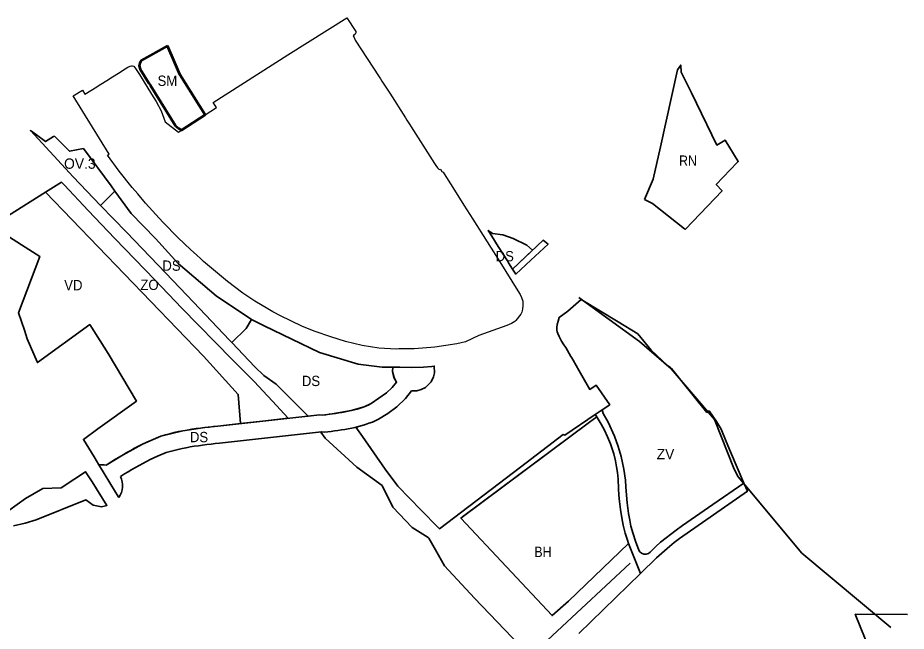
# Model space of a CAD drawing. Extents: x -650276 to -642489, y -1074311 to -1066658.
# Drawn here: x -647227 to -646196, y -1072424 to -1071711 of the extents above; entities that cross this region are included whole.
import ezdxf

# ---------------------------------------------------------------- set-up
doc = ezdxf.new("R2010")
doc.units = 0
doc.header["$LTSCALE"] = 4.8
for name, color, linetype, lineweight in [('1', 7, 'Continuous', 35), ('11', 7, 'Continuous', 35), ('15', 7, 'Continuous', 35), ('18', 7, 'Continuous', 35), ('24', 7, 'Continuous', 35), ('35', 7, 'Continuous', 35), ('40', 7, 'Continuous', 35), ('42', 7, 'Continuous', 35), ('48', 7, 'Continuous', 35), ('54', 7, 'Continuous', 35), ('60', 7, 'Continuous', 53), ('61', 7, 'Continuous', 25), ('7', 7, 'Continuous', 35)]:
    doc.layers.add(name, color=color, linetype=linetype, lineweight=lineweight)
doc.layers.add('62', color=7, linetype='Continuous')

msp = doc.modelspace()

# ---------------------------------------------------------------- linework, layer by layer
at = {"layer": '1'}
msp.add_lwpolyline([(-646606.848, -1072405.785), (-646587.666, -1072389.082), (-646518.208, -1072321.92), (-646519.417, -1072318.408), (-646522.007, -1072309.932), (-646524.282, -1072300.849), (-646526, -1072292.201), (-646527.5, -1072282.657), (-646528.566, -1072273.308), (-646529.182, -1072265.941), (-646529.607, -1072258.124), (-646530.188, -1072247.442), (-646530.892, -1072239.747), (-646531.93, -1072232.861), (-646533.286, -1072226.031), (-646535.344, -1072217.844), (-646536.772, -1072213.218), (-646539.168, -1072206.122), (-646539.168, -1072206.122), (-646542.484, -1072197.985), (-646546.09, -1072190.428), (-646549.793, -1072183.38), (-646554.56, -1072175.629), (-646555.051, -1072174.933), (-646563.299, -1072181.091), (-646710.684, -1072291.133), (-646712.634, -1072292.59)], close=True, dxfattribs=at)
at = {"layer": '11'}
for points in [[(-647184.81, -1071848.61), (-647185.62, -1071849.12), (-647194.96, -1071854.93), (-647205.62, -1071847.24), (-647212.66, -1071842.15), (-647163.08, -1071896.13), (-647131.146, -1071929.146)], [(-647131.146, -1071929.146), (-647114.479, -1071912.479), (-647118.79, -1071906.59), (-647151.07, -1071863.08), (-647167.15, -1071866.22), (-647184.81, -1071848.61)]]:
    msp.add_lwpolyline(points, dxfattribs=at)
at = {"layer": '15'}
for points in [[(-646652.864, -1072003.075), (-646617.21, -1071969.689), (-646611.438, -1071974.36), (-646631.409, -1071992.798), (-646649.112, -1072009.049)], [(-646529.182, -1072265.941), (-646528.566, -1072273.308), (-646527.5, -1072282.657), (-646526, -1072292.201), (-646524.282, -1072300.849), (-646522.007, -1072309.932), (-646519.417, -1072318.408), (-646518.208, -1072321.92), (-646504.244, -1072357.026), (-646485.656, -1072338.908), (-646473.069, -1072327.765), (-646465.227, -1072321.127), (-646459.03, -1072316.137), (-646380.12, -1072261.44), (-646384.056, -1072252.138), (-646420.085, -1072276.737), (-646455.557, -1072301.131), (-646462.79, -1072306.784), (-646480.923, -1072320.667), (-646486.273, -1072325.526), (-646492.813, -1072332.07), (-646494.794, -1072333.558), (-646497.569, -1072334.55), (-646500.244, -1072334.45), (-646503.018, -1072333.459), (-646504.802, -1072331.971), (-646506.189, -1072329.889), (-646509.954, -1072319.377), (-646512.729, -1072311.048), (-646515.305, -1072301.925), (-646516.692, -1072294.983), (-646518.079, -1072287.051), (-646519.756, -1072274.861), (-646521.051, -1072256.707), (-646521.646, -1072248.378), (-646523.628, -1072235.883), (-646526.798, -1072221.011), (-646530.167, -1072209.31), (-646534.527, -1072197.411), (-646541.822, -1072181.102), (-646547.606, -1072170.835), (-646548.676, -1072166.737), (-646556.693, -1072172.16), (-646555.051, -1072174.933), (-646554.56, -1072175.629), (-646549.793, -1072183.38), (-646546.09, -1072190.428), (-646542.484, -1072197.985), (-646539.168, -1072206.122), (-646536.772, -1072213.218), (-646535.344, -1072217.844), (-646533.286, -1072226.031), (-646531.93, -1072232.861), (-646530.892, -1072239.747), (-646530.188, -1072247.442), (-646529.607, -1072258.124)]]:
    msp.add_lwpolyline(points, close=True, dxfattribs=at)
at = {"layer": '18'}
for points in [[(-647053.43, -1071743.63), (-647083.97, -1071760.74), (-647084.95, -1071761.98), (-647085.71, -1071763.75), (-647086.19, -1071766.95), (-647085.25, -1071770.69), (-647074.99, -1071786.99), (-647073.19, -1071789.9), (-647044.12, -1071836.68)], [(-647009.514, -1071823.81), (-647016.12, -1071813.35), (-647039.14, -1071776.9), (-647044.83, -1071763.37), (-647053.43, -1071743.63)], [(-647044.12, -1071836.68), (-647040.2, -1071839.6), (-647037.23, -1071841.82), (-647009.514, -1071823.81)]]:
    msp.add_lwpolyline(points, dxfattribs=at)
at = {"layer": '24'}
for p, q in [((-646978.602, -1072088.66), (-646951.95, -1072116.84)), ((-647113.646, -1072224.274), (-647124.81, -1072231.168))]:
    msp.add_line(p, q, dxfattribs=at)
for points in [[(-646996.8, -1072034.35), (-647040.89, -1071996.58), (-647067.53, -1071967.54), (-647095.51, -1071938.39), (-647114.479, -1071912.479), (-647131.146, -1071929.146), (-647101.07, -1071960.24)], [(-647101.07, -1071960.24), (-647055.16, -1072007.74), (-647023.04, -1072041.63), (-646981.35, -1072085.77), (-646978.602, -1072088.66), (-646962.041, -1072072.379), (-646956.04, -1072061.95), (-646996.8, -1072034.35)], [(-646790.432, -1072129.195), (-646791.977, -1072122.305), (-646791.84, -1072117.172), (-646804.27, -1072116.98), (-646832.01, -1072113.66), (-646876.83, -1072100.12), (-646941.054, -1072069.172), (-646956.04, -1072061.95), (-646962.041, -1072072.379), (-646978.602, -1072088.66)], [(-646816.74, -1072159.571), (-646799, -1072147), (-646792.58, -1072140.847), (-646787.481, -1072134.643), (-646790.343, -1072129.36), (-646791.977, -1072122.305), (-646791.84, -1072117.172), (-646783.449, -1072117.302), (-646769.668, -1072117.517), (-646756.298, -1072117), (-646746.547, -1072116.221), (-646743.596, -1072115.985), (-646743.411, -1072123.612), (-646744.554, -1072128.415), (-646747.39, -1072134.069), (-646750.164, -1072137.467), (-646753.929, -1072140.612), (-646758.736, -1072143.137), (-646763.959, -1072144.535), (-646770.057, -1072144.677), (-646777.129, -1072153.576), (-646787.223, -1072163.402), (-646797.713, -1072171.151), (-646808.466, -1072177.78)], [(-646808.466, -1072177.78), (-646797.713, -1072171.151), (-646787.223, -1072163.402), (-646777.129, -1072153.576), (-646770.057, -1072144.677), (-646763.959, -1072144.535), (-646758.736, -1072143.137), (-646753.929, -1072140.612), (-646750.164, -1072137.467), (-646747.39, -1072134.069), (-646744.554, -1072128.415), (-646743.411, -1072123.612), (-646743.596, -1072115.985), (-646746.547, -1072116.221), (-646756.298, -1072117), (-646769.668, -1072117.517), (-646783.449, -1072117.302), (-646791.84, -1072117.172), (-646791.977, -1072122.305), (-646790.343, -1072129.36), (-646787.481, -1072134.643), (-646792.58, -1072140.847), (-646799, -1072147), (-646816.74, -1072159.571)], [(-646951.95, -1072116.84), (-646941.45, -1072126.84), (-646927.14, -1072136.74), (-646891.05, -1072172.79), (-646890.044, -1072174.056), (-646876.712, -1072172.592), (-646873.495, -1072172.799), (-646862.09, -1072171.444), (-646840.102, -1072167.623), (-646825.169, -1072163.164), (-646816.74, -1072159.571), (-646799, -1072147), (-646792.58, -1072140.847), (-646787.481, -1072134.643), (-646790.432, -1072129.195)], [(-647124.81, -1072231.168), (-647113.646, -1072224.274), (-647109.342, -1072221.634), (-647104.989, -1072219.005), (-647100.583, -1072216.405), (-647096.114, -1072213.845), (-647091.574, -1072211.346), (-647086.955, -1072208.921), (-647082.249, -1072206.591), (-647077.456, -1072204.373), (-647072.72, -1072202.352), (-647060.973, -1072197.439), (-647055.906, -1072195.893), (-647050.82, -1072194.5), (-647045.722, -1072193.245), (-647040.618, -1072192.117), (-647035.515, -1072191.104), (-647030.417, -1072190.192), (-647025.33, -1072189.37), (-647020.254, -1072188.623), (-647015.192, -1072187.939), (-647010.148, -1072187.308), (-647005.124, -1072186.715), (-647000.12, -1072186.148), (-646995.137, -1072185.597), (-646876.712, -1072172.592), (-646873.495, -1072172.799), (-646869.667, -1072172.366), (-646865.866, -1072171.917), (-646862.09, -1072171.444), (-646858.343, -1072170.937), (-646854.627, -1072170.389), (-646850.941, -1072169.791), (-646847.291, -1072169.137), (-646843.678, -1072168.416), (-646840.102, -1072167.623), (-646836.573, -1072166.751), (-646833.091, -1072165.791), (-646829.66, -1072164.739), (-646826.287, -1072163.588), (-646822.975, -1072162.332), (-646819.733, -1072160.968), (-646816.74, -1072159.571)], [(-646816.74, -1072159.571), (-646819.733, -1072160.968), (-646822.975, -1072162.332), (-646826.287, -1072163.588), (-646829.66, -1072164.739), (-646833.091, -1072165.791), (-646836.573, -1072166.751), (-646840.102, -1072167.623), (-646843.678, -1072168.416), (-646847.291, -1072169.137), (-646850.941, -1072169.791), (-646854.627, -1072170.389), (-646858.343, -1072170.937), (-646862.09, -1072171.444), (-646865.866, -1072171.917), (-646869.667, -1072172.366), (-646873.495, -1072172.799), (-646876.712, -1072172.592), (-646995.137, -1072185.597), (-647000.12, -1072186.148), (-647005.124, -1072186.715), (-647010.148, -1072187.308), (-647015.192, -1072187.939), (-647020.254, -1072188.623), (-647025.33, -1072189.37), (-647030.417, -1072190.192), (-647035.515, -1072191.104), (-647040.618, -1072192.117), (-647045.722, -1072193.245), (-647050.82, -1072194.5), (-647055.906, -1072195.893), (-647060.973, -1072197.439), (-647072.72, -1072202.352), (-647077.456, -1072204.373), (-647082.249, -1072206.591), (-647086.955, -1072208.921), (-647091.574, -1072211.346), (-647096.114, -1072213.845), (-647100.583, -1072216.405), (-647104.989, -1072219.005), (-647109.342, -1072221.634), (-647113.646, -1072224.274)], [(-646808.466, -1072177.78), (-646811.621, -1072179.254), (-646815.549, -1072180.906), (-646819.509, -1072182.408), (-646823.496, -1072183.769), (-646827.501, -1072184.997), (-646831.517, -1072186.103), (-646835.538, -1072187.097), (-646839.556, -1072187.988), (-646843.569, -1072188.789), (-646847.575, -1072189.507), (-646851.567, -1072190.155), (-646855.545, -1072190.741), (-646859.506, -1072191.276), (-646863.448, -1072191.771), (-646867.371, -1072192.234), (-646871.271, -1072192.675), (-646874.517, -1072192.471), (-646992.937, -1072205.475), (-646997.894, -1072206.024), (-647002.826, -1072206.583), (-647007.734, -1072207.162), (-647012.612, -1072207.773), (-647017.46, -1072208.427), (-647022.278, -1072209.136), (-647027.061, -1072209.91), (-647031.807, -1072210.758), (-647036.512, -1072211.693), (-647041.174, -1072212.723), (-647045.786, -1072213.858), (-647050.344, -1072215.107), (-647054.841, -1072216.479), (-647064.868, -1072220.746), (-647069.33, -1072222.651), (-647073.611, -1072224.631), (-647077.867, -1072226.739), (-647082.102, -1072228.962), (-647086.322, -1072231.285), (-647090.531, -1072233.695), (-647094.737, -1072236.177), (-647098.944, -1072238.718), (-647103.164, -1072241.306), (-647108.131, -1072244.373)], [(-646874.517, -1072192.471), (-646871.271, -1072192.675), (-646867.371, -1072192.234), (-646863.448, -1072191.771), (-646859.506, -1072191.276), (-646855.545, -1072190.741), (-646851.567, -1072190.155), (-646847.575, -1072189.507), (-646843.569, -1072188.789), (-646839.556, -1072187.988), (-646835.538, -1072187.097), (-646831.517, -1072186.103), (-646827.501, -1072184.997), (-646823.496, -1072183.769), (-646819.509, -1072182.408), (-646815.549, -1072180.906), (-646811.621, -1072179.254), (-646808.466, -1072177.78)], [(-647108.131, -1072244.373), (-647103.164, -1072241.306), (-647098.944, -1072238.718), (-647094.737, -1072236.177), (-647090.531, -1072233.695), (-647086.322, -1072231.285), (-647082.102, -1072228.962), (-647077.867, -1072226.739), (-647073.611, -1072224.631), (-647069.33, -1072222.651), (-647064.868, -1072220.746), (-647054.841, -1072216.479), (-647050.344, -1072215.107), (-647045.786, -1072213.858), (-647041.174, -1072212.723), (-647036.512, -1072211.693), (-647031.807, -1072210.758), (-647027.061, -1072209.91), (-647022.278, -1072209.136), (-647017.46, -1072208.427), (-647012.612, -1072207.773), (-647007.734, -1072207.162), (-647002.826, -1072206.583), (-646997.894, -1072206.024), (-646992.937, -1072205.475), (-646874.517, -1072192.471)], [(-647232.368, -1072301.4), (-647218.5, -1072298.335), (-647205.975, -1072294.599), (-647148.171, -1072271.47), (-647139.697, -1072277.484), (-647130.12, -1072279.44), (-647123.774, -1072277.899), (-647141.05, -1072250.54), (-647148.71, -1072238.76), (-647148.71, -1072238.76), (-647160.91, -1072246.82), (-647176.7, -1072257.24), (-647198.3, -1072258.09), (-647218.35, -1072269.67), (-647237.6, -1072283.78)], [(-647109.812, -1072268.588), (-647110.55, -1072267.42), (-647119.07, -1072253.56), (-647128.07, -1072238.83), (-647133, -1072230.754)], [(-647133, -1072230.754), (-647128.07, -1072238.83), (-647119.07, -1072253.56), (-647110.55, -1072267.42), (-647109.812, -1072268.588)]]:
    msp.add_lwpolyline(points, dxfattribs=at)
msp.add_lwpolyline([(-646652.18, -1071967.73), (-646636.01, -1071975.35), (-646629.655, -1071981.343), (-646652.864, -1072003.075), (-646657.32, -1071995.98), (-646658.79, -1071993.62), (-646669.31, -1071976.77), (-646676.79, -1071964.97), (-646681.07, -1071958.16), (-646675.99, -1071961.64), (-646663.87, -1071963.26)], close=True, dxfattribs=at)
for centre, start, end in [((-646767.624, -1072120.384), 264.28146, 264.89913), ((-647130.12, -1072255.012), 77.44425, 96.77054), ((-647130.12, -1072255.012), 77.44425, 96.77054), ((-647130.12, -1072255.012), 326.23773, 25.81772), ((-647130.12, -1072255.012), 326.23773, 25.81772)]:
    msp.add_arc(centre, 24.428, start, end, dxfattribs=at)
at = {"layer": '35'}
msp.add_lwpolyline([(-647249.92, -1071958.12), (-647201.53, -1071988.71), (-647226.41, -1072054.11), (-647219.64, -1072074.29), (-647216.23, -1072084.14), (-647204.78, -1072110.92), (-647204.38, -1072111.87), (-647143.76, -1072067.69), (-647122.33, -1072101.34), (-647089.54, -1072156.53), (-647134.17, -1072188.95), (-647151.05, -1072201.21), (-647138.65, -1072221.5), (-647133, -1072230.754), (-647124.81, -1072231.168), (-647104.989, -1072219.005), (-647082.249, -1072206.591), (-647060.973, -1072197.439), (-647035.515, -1072191.104), (-647010.148, -1072187.308), (-646995.137, -1072185.597), (-646968.503, -1072182.672), (-646971.283, -1072148.82), (-647011.762, -1072104.502), (-647194.903, -1071913.941), (-647238.1, -1071941)], dxfattribs=at)
at = {"layer": '40'}
msp.add_lwpolyline([(-646507.28, -1072078.4), (-646530.073, -1072064.559), (-646573.05, -1072038.46), (-646588.75, -1072052.06), (-646598.827, -1072059.244), (-646599.86, -1072063.71), (-646601, -1072067.55), (-646601.42, -1072071.01), (-646601.16, -1072074.07), (-646600.8, -1072075.94), (-646600.22, -1072077.86), (-646598.67, -1072081.55), (-646595.86, -1072086.82), (-646593.13, -1072091.01), (-646591.02, -1072094.4), (-646585.08, -1072104.81), (-646583.9, -1072106.42), (-646577.41, -1072117.76), (-646577.08, -1072118.7), (-646563.11, -1072143.03), (-646555.49, -1072138.17), (-646539.94, -1072160.83), (-646548.676, -1072166.737), (-646547.606, -1072170.835), (-646541.822, -1072181.102), (-646534.527, -1072197.411), (-646530.167, -1072209.31), (-646526.798, -1072221.011), (-646523.628, -1072235.883), (-646521.646, -1072248.378), (-646521.051, -1072256.707), (-646519.756, -1072274.861), (-646518.079, -1072287.051), (-646516.692, -1072294.983), (-646515.305, -1072301.925), (-646512.729, -1072311.048), (-646509.954, -1072319.377), (-646506.189, -1072329.889), (-646504.802, -1072331.971), (-646503.018, -1072333.459), (-646500.244, -1072334.45), (-646497.569, -1072334.55), (-646494.794, -1072333.558), (-646492.813, -1072332.07), (-646486.273, -1072325.526), (-646480.923, -1072320.667), (-646462.79, -1072306.784), (-646455.557, -1072301.131), (-646420.085, -1072276.737), (-646384.056, -1072252.138), (-646391.77, -1072233.91), (-646399.6, -1072215.39), (-646404.67, -1072203.42), (-646410.68, -1072189.36), (-646415.84, -1072180.43), (-646424.56, -1072167.96), (-646426.98, -1072169.74), (-646455.75, -1072134.29), (-646468.35, -1072118.76), (-646469.41, -1072117.44), (-646472.72, -1072115.38), (-646491.69, -1072097.45)], close=True, dxfattribs=at)
at = {"layer": '42'}
msp.add_lwpolyline([(-647011.762, -1072104.502), (-646971.283, -1072148.82), (-646968.503, -1072182.672), (-646942.928, -1072179.864), (-646913.373, -1072176.618), (-646931.653, -1072156.802), (-646942.78, -1072144.74), (-646952.48, -1072134.22), (-646964.8, -1072121.83), (-646977.59, -1072108.96), (-646978.45, -1072108.09), (-647036.8, -1072048.41), (-647068.31, -1072015.68), (-647114.59, -1071967.77), (-647145.38, -1071935), (-647173.14, -1071905.45), (-647174.57, -1071904.06), (-647176.32, -1071902.3), (-647194.903, -1071913.941)], close=True, dxfattribs=at)
msp.add_lwpolyline([(-646575.792, -1072426.789), (-646504.244, -1072357.026), (-646518.208, -1072321.92), (-646587.666, -1072389.082), (-646606.848, -1072405.785), (-646712.634, -1072292.59), (-646563.299, -1072181.091), (-646555.051, -1072174.933), (-646556.693, -1072172.16), (-646592.2, -1072196.17), (-646593.85, -1072195.48), (-646643.55, -1072233.5), (-646737.449, -1072305.019), (-646738.951, -1072303.49), (-646758.684, -1072283.41), (-646785.958, -1072255.505), (-646800.76, -1072235.668), (-646826.893, -1072197.582), (-646832.718, -1072189.697), (-646834.279, -1072186.818), (-646833.373, -1072186.562), (-646835.538, -1072187.097), (-646839.556, -1072187.988), (-646843.569, -1072188.789), (-646847.575, -1072189.507), (-646851.567, -1072190.155), (-646855.545, -1072190.741), (-646859.506, -1072191.276), (-646863.448, -1072191.771), (-646867.371, -1072192.234), (-646871.271, -1072192.675), (-646874.517, -1072192.471), (-646875.509, -1072192.58), (-646870.21, -1072199.51), (-646833.75, -1072233.32), (-646803.98, -1072254.74), (-646791.59, -1072279.78), (-646769.24, -1072303.65), (-646750.58, -1072315.02), (-646750.12, -1072315.82), (-646742.32, -1072329.62), (-646731.82, -1072348.2), (-646696.83, -1072385.81), (-646618.158, -1072468.098)], dxfattribs=at)
at = {"layer": '48'}
msp.add_lwpolyline([(-646194.19, -1072404.62), (-646254.75, -1072404.25), (-646243.17, -1072432.88), (-646282.47, -1072474.34), (-646328.45, -1072504.81), (-646307.6, -1072547.74), (-646236.97, -1072678.31), (-646171.72, -1072803.51)], dxfattribs=at)
at = {"layer": '54'}
for points in [[(-646395.588, -1072235.707), (-646418.384, -1072178.078), (-646468.581, -1072119.193), (-646505.263, -1072087.337), (-646575.731, -1072036.175)], [(-646395.588, -1072235.707), (-646390.794, -1072244.804), (-646316.998, -1072333.174), (-646213.65, -1072419.58)], [(-646516, -1072345), (-646685.823, -1072502.987), (-646914.429, -1072678.004), (-647018.969, -1072761.795), (-647092.194, -1072861.614), (-647161.068, -1073050.946)]]:
    msp.add_lwpolyline(points, dxfattribs=at)
at = {"layer": '60'}
for points in [[(-647053.43, -1071743.63), (-647083.97, -1071760.74), (-647084.95, -1071761.98), (-647085.71, -1071763.75), (-647086.19, -1071766.95), (-647085.25, -1071770.69), (-647074.99, -1071786.99)], [(-647009.514, -1071823.81), (-647016.12, -1071813.35), (-647039.14, -1071776.9), (-647044.83, -1071763.37), (-647053.43, -1071743.63)], [(-647074.99, -1071786.99), (-647073.19, -1071789.9), (-647044.12, -1071836.68)], [(-647044.12, -1071836.68), (-647040.2, -1071839.6), (-647037.23, -1071841.82), (-647009.514, -1071823.81)]]:
    msp.add_lwpolyline(points, dxfattribs=at)
at = {"layer": '61'}
for points in [[(-646641.16, -1072049.51), (-646641.59, -1072051.75), (-646642.05, -1072053.14), (-646643.11, -1072055.41), (-646648.78, -1072062.89), (-646650.1, -1072063.91), (-646653.86, -1072066.41), (-646659.309, -1072068.883), (-646691.77, -1072080.37), (-646707.5, -1072087.64), (-646717.55, -1072090), (-646742.95, -1072093.96), (-646767.01, -1072095.86), (-646771.52, -1072095.92), (-646781.75, -1072096.04), (-646784.76, -1072096.01), (-646787.8, -1072096.24), (-646807.9, -1072095.03), (-646827.46, -1072092.09), (-646846.81, -1072087.28), (-646863.68, -1072082.09), (-646881.98, -1072075.61), (-646896.84, -1072069.83), (-646922.95, -1072057.25), (-646929.53, -1072053.65), (-646931, -1072052.81), (-646936.81, -1072049.5), (-646952.07, -1072040.55), (-646966.13, -1072031.23), (-646983.88, -1072017.52), (-647011.61, -1071994.42), (-647015.13, -1071991.01), (-647019.3, -1071987.12), (-647026.77, -1071980.29), (-647041.08, -1071966.71), (-647059.01, -1071948.52), (-647079.15, -1071926.49), (-647088.04, -1071915.77), (-647094.25, -1071908.29), (-647109.58, -1071889.27), (-647123, -1071870.89), (-647121.15, -1071869.68), (-647162.98, -1071801.68), (-647152.08, -1071795.15), (-647149.32, -1071799.92), (-647135.34, -1071791.17), (-647132.63, -1071789.47), (-647121.76, -1071782.65), (-647119.06, -1071780.95), (-647108.21, -1071774.17), (-647105.49, -1071772.47), (-647099.39, -1071768.65), (-647096.58, -1071767.23), (-647095.35, -1071766.89), (-647093.94, -1071766.95), (-647092.65, -1071767.48), (-647091.55, -1071768.46), (-647090.45, -1071769.99), (-647085.97, -1071777.09), (-647081.6, -1071784.03), (-647071.99, -1071799.81), (-647066.76, -1071808.54), (-647060.7, -1071819.12), (-647056.31, -1071832.13), (-647040.52, -1071843.958), (-647037.23, -1071841.82), (-646996.65, -1071815.45), (-647000.4, -1071809.69), (-646913.82, -1071754.1), (-646845.08, -1071711.06), (-646834.86, -1071727.2), (-646834.66, -1071728.69), (-646835.33, -1071730.32), (-646837.92, -1071732.14), (-646836.62, -1071734.14), (-646835.35, -1071737.24), (-646807.7, -1071779.69), (-646806.22, -1071781.97), (-646804.6, -1071784.61), (-646795.36, -1071798.85), (-646777.21, -1071827.55), (-646775.63, -1071830.04), (-646772.5, -1071834.88), (-646770.65, -1071837.91), (-646743.34, -1071880.3), (-646741.81, -1071882.7), (-646740.07, -1071885.5), (-646737.81, -1071887.58), (-646736.61, -1071887.04), (-646734.75, -1071889.65), (-646733.38, -1071890.49), (-646732.05, -1071892.58), (-646721.96, -1071908.47), (-646709.19, -1071928.91), (-646698.88, -1071945.32), (-646665.78, -1071998.02), (-646648.65, -1072025.26), (-646644.03, -1072032.61), (-646642.27, -1072036.3)], [(-646642.27, -1072036.3), (-646640.88, -1072040.43), (-646640.7, -1072041.21), (-646640.73, -1072046.02), (-646640.73, -1072046.02), (-646641.16, -1072049.51)]]:
    msp.add_lwpolyline(points, dxfattribs=at)
at = {"layer": '7'}
for points in [[(-646453.04, -1071956.3), (-646451.87, -1071956.88), (-646409.4, -1071912.17), (-646416.2, -1071904.81), (-646391.83, -1071879.32), (-646390.732, -1071878.171), (-646405.99, -1071853.26), (-646415.46, -1071859.05), (-646445.115, -1071798.418), (-646456.96, -1071774.2), (-646457.52, -1071765.98), (-646461.09, -1071771.76), (-646480.81, -1071861.18), (-646489.34, -1071898.61), (-646499.741, -1071922.455)], [(-646499.741, -1071922.455), (-646490.111, -1071926.754), (-646453.04, -1071956.3)]]:
    msp.add_lwpolyline(points, dxfattribs=at)

# ---------------------------------------------------------------- texts
at = {"layer": '62'}
for s, width, p in [('SM', 0.95, (-647064.938, -1071790.245)), ('RN', 0.9, (-646459.448, -1071883.14)), ('DS', 0.95, (-646672.386, -1071994.148)), ('DS', 0.95, (-647059.386, -1072005.148)), ('VD', 0.95, (-647173.311, -1072027.838)), ('ZO', 0.95, (-647084.886, -1072027.486)), ('DS', 0.95, (-646897.386, -1072139.148)), ('DS', 0.95, (-647027.378, -1072204.379)), ('BH', 0.9, (-646627.48, -1072337.818))]:
    msp.add_text(s, height=12, dxfattribs=dict(at, width=width)).set_placement(p)
for s, p in [('OV.3', (-647173.505, -1071886.6)), ('ZV', (-646485.386, -1072224.148))]:
    msp.add_text(s, height=12, dxfattribs=at).set_placement(p)

doc.saveas('drawing.dxf')
